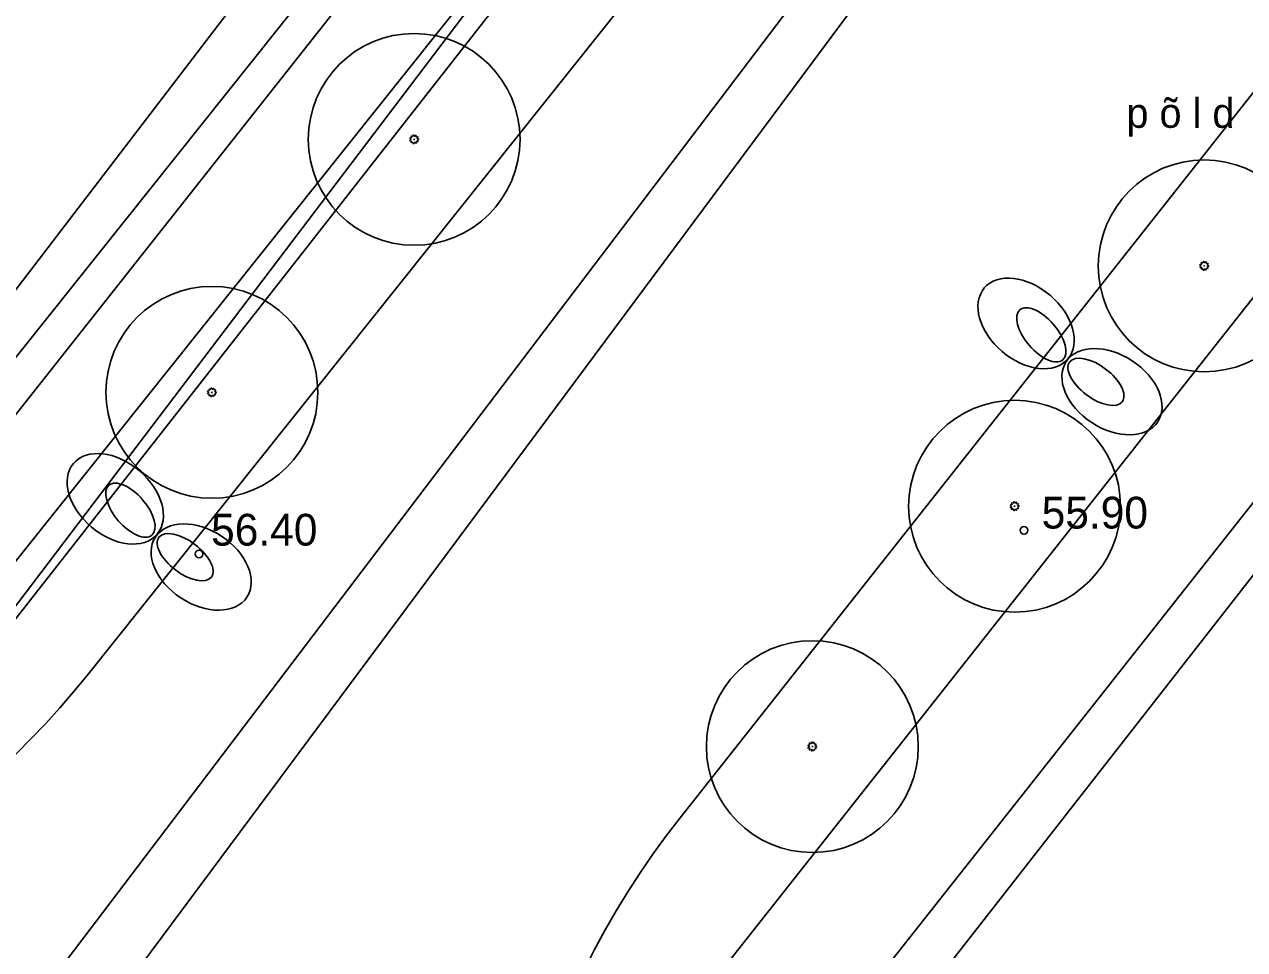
# Model space of a CAD drawing. Extents: x 9156 to 9809, y 2728 to 4000.
# Drawn here: x 9440.27 to 9469.07, y 3522.78 to 3544.62 of the extents above; entities that cross this region are included whole.
import ezdxf

# ---------------------------------------------------------------- set-up
doc = ezdxf.new("R2010")
doc.units = 0
for name, color, linetype in [('Level 12', 7, 'Continuous'), ('Level 14', 7, 'Continuous'), ('Level 15', 7, 'Continuous'), ('Level 16', 7, 'Continuous'), ('Level 17', 7, 'Continuous'), ('Level 18', 7, 'Continuous'), ('Level 54', 7, 'Continuous'), ('Level 56', 7, 'Continuous'), ('Level 7', 7, 'Continuous'), ('Level 8', 7, 'Continuous'), ('Level 9', 7, 'Continuous')]:
    doc.layers.add(name, color=color, linetype=linetype)

msp = doc.modelspace()

# ---------------------------------------------------------------- linework, layer by layer
at = {"layer": 'Level 12'}
msp.add_line((9472.329, 3573.455), (9435.481, 3524.854), dxfattribs=at)
at = {"layer": 'Level 14'}
msp.add_line((9427.489, 3501.526), (9484.383, 3578.032), dxfattribs=at)
at = {"layer": 'Level 15'}
msp.add_line((9435.211, 3524.4), (9458.77, 3554.464), dxfattribs=at)
at = {"layer": 'Level 16'}
msp.add_line((9432.07, 3510.41), (9469.372, 3559.57), dxfattribs=at)
at = {"layer": 'Level 17'}
for p, q in [((9504.212, 3582.406), (9456.099, 3521.498)), ((9506.566, 3580.546), (9458.461, 3519.649)), ((9427.374, 3519.354), (9458.182, 3558.332)), ((9428.56, 3522.344), (9455.51, 3556.115)), ((9432.973, 3523.064), (9457.855, 3554.244))]:
    msp.add_line(p, q, dxfattribs=at)
at = {"layer": 'Level 18'}
for p, q in [((9501.857, 3584.265), (9455.749, 3525.895)), ((9441.751, 3529.254), (9460.2, 3552.373))]:
    msp.add_line(p, q, dxfattribs=at)
for centre, start, end in [((9426.118, 3541.729), 233.8069, 321.4101), ((9471.443, 3513.498), 141.6938, 238.8019)]:
    msp.add_arc(centre, 20, start, end, dxfattribs=at)
at = {"layer": 'Level 54'}
for centre in [(9463.865, 3532.678), (9444.395, 3532.122)]:
    msp.add_circle(centre, 0.0909, dxfattribs=at)
at = {"layer": 'Level 56'}
for p, q in [((9501.857, 3584.265), (9455.749, 3525.895)), ((9504.212, 3582.406), (9456.099, 3521.498)), ((9506.566, 3580.546), (9458.461, 3519.649)), ((9428.56, 3522.344), (9455.51, 3556.115)), ((9432.973, 3523.064), (9457.855, 3554.244)), ((9441.751, 3529.254), (9460.2, 3552.373))]:
    msp.add_line(p, q, dxfattribs=at)
for centre, start, end in [((9426.118, 3541.729), 233.8069, 321.4101), ((9471.443, 3513.498), 141.6938, 238.8019)]:
    msp.add_arc(centre, 20, start, end, dxfattribs=at)
at = {"layer": 'Level 7'}
for p, q in [((9508.911, 3582.331), (9456.401, 3515.151)), ((9428.759, 3523.586), (9464.86, 3570.761))]:
    msp.add_line(p, q, dxfattribs=at)
at = {"layer": 'Level 8'}
for centre, major_axis, ratio in [((9463.915, 3537.563), (0.986, -0.837), 0.674652), ((9463.915, 3537.563), (0.986, -0.837), 0.674652), ((9463.915, 3537.563), (0.986, -0.837), 0.674652), ((9463.915, 3537.563), (0.986, -0.837), 0.674652), ((9464.274, 3537.294), (0.507, -0.589), 0.486914), ((9464.274, 3537.294), (0.507, -0.589), 0.486914), ((9464.274, 3537.294), (0.507, -0.589), 0.486914), ((9464.274, 3537.294), (0.507, -0.589), 0.486914), ((9465.942, 3535.952), (-1.081, 0.71), 0.674652), ((9465.942, 3535.952), (-1.081, 0.71), 0.674652), ((9465.942, 3535.952), (-1.081, 0.71), 0.674652), ((9465.942, 3535.952), (-1.081, 0.71), 0.674652), ((9465.564, 3536.185), (-0.62, 0.47), 0.486914), ((9465.564, 3536.185), (-0.62, 0.47), 0.486914), ((9465.564, 3536.185), (-0.62, 0.47), 0.486914), ((9465.564, 3536.185), (-0.62, 0.47), 0.486914), ((9442.418, 3533.423), (0.986, -0.837), 0.674652), ((9442.418, 3533.423), (0.986, -0.837), 0.674652), ((9442.418, 3533.423), (0.986, -0.837), 0.674652), ((9442.418, 3533.423), (0.986, -0.837), 0.674652), ((9442.776, 3533.154), (0.507, -0.589), 0.486914), ((9442.776, 3533.154), (0.507, -0.589), 0.486914), ((9442.776, 3533.154), (0.507, -0.589), 0.486914), ((9442.776, 3533.154), (0.507, -0.589), 0.486914), ((9444.445, 3531.812), (-1.081, 0.71), 0.674652), ((9444.445, 3531.812), (-1.081, 0.71), 0.674652), ((9444.445, 3531.812), (-1.081, 0.71), 0.674652), ((9444.445, 3531.812), (-1.081, 0.71), 0.674652), ((9444.067, 3532.045), (-0.62, 0.47), 0.486914), ((9444.067, 3532.045), (-0.62, 0.47), 0.486914), ((9444.067, 3532.045), (-0.62, 0.47), 0.486914), ((9444.067, 3532.045), (-0.62, 0.47), 0.486914)]:
    msp.add_ellipse(centre, major_axis=major_axis, ratio=ratio, dxfattribs=at)
at = {"layer": 'Level 9'}
for p, q in [((9449.394, 3541.92), (9449.372, 3541.923)), ((9449.372, 3541.894), (9449.393, 3541.898)), ((9449.38, 3541.95), (9449.4, 3541.942)), ((9449.4, 3541.876), (9449.38, 3541.866)), ((9449.395, 3541.843), (9449.412, 3541.857)), ((9449.412, 3541.96), (9449.396, 3541.974)), ((9449.417, 3541.993), (9449.429, 3541.974)), ((9449.429, 3541.842), (9449.417, 3541.824)), ((9449.45, 3541.984), (9449.443, 3542.005)), ((9449.443, 3541.812), (9449.449, 3541.833)), ((9449.482, 3541.907), (9449.461, 3541.907)), ((9449.472, 3541.829), (9449.471, 3541.808)), ((9449.472, 3542.009), (9449.472, 3541.987)), ((9449.472, 3541.897), (9449.472, 3541.918)), ((9449.493, 3541.984), (9449.499, 3542.005)), ((9449.499, 3541.811), (9449.494, 3541.833)), ((9449.514, 3541.841), (9449.526, 3541.823)), ((9449.525, 3541.993), (9449.515, 3541.974)), ((9449.531, 3541.96), (9449.548, 3541.974)), ((9449.548, 3541.843), (9449.532, 3541.858)), ((9449.563, 3541.95), (9449.544, 3541.94)), ((9449.544, 3541.876), (9449.564, 3541.867)), ((9449.55, 3541.919), (9449.571, 3541.923)), ((9449.571, 3541.895), (9449.55, 3541.898)), ((9468.041, 3538.934), (9468.019, 3538.937)), ((9468.019, 3538.908), (9468.04, 3538.912)), ((9468.027, 3538.964), (9468.047, 3538.956)), ((9468.047, 3538.89), (9468.027, 3538.88)), ((9468.042, 3538.857), (9468.059, 3538.871)), ((9468.059, 3538.974), (9468.043, 3538.988)), ((9468.064, 3539.007), (9468.075, 3538.988)), ((9468.076, 3538.856), (9468.064, 3538.838)), ((9468.097, 3538.998), (9468.09, 3539.019)), ((9468.129, 3538.921), (9468.108, 3538.921)), ((9468.118, 3539.023), (9468.118, 3539.001)), ((9468.119, 3538.911), (9468.119, 3538.932)), ((9468.14, 3538.998), (9468.146, 3539.019)), ((9468.161, 3538.856), (9468.173, 3538.838)), ((9468.172, 3539.007), (9468.162, 3538.988)), ((9468.178, 3538.974), (9468.194, 3538.988)), ((9468.195, 3538.857), (9468.179, 3538.872)), ((9468.21, 3538.964), (9468.191, 3538.954)), ((9468.191, 3538.89), (9468.21, 3538.882)), ((9468.197, 3538.933), (9468.218, 3538.937)), ((9468.218, 3538.909), (9468.197, 3538.912)), ((9468.09, 3538.826), (9468.096, 3538.847)), ((9468.118, 3538.844), (9468.118, 3538.822)), ((9468.146, 3538.826), (9468.141, 3538.847)), ((9444.607, 3535.979), (9444.627, 3535.97)), ((9444.639, 3535.989), (9444.622, 3536.003)), ((9444.643, 3536.021), (9444.655, 3536.003)), ((9444.676, 3536.012), (9444.67, 3536.033)), ((9444.698, 3536.037), (9444.698, 3536.015)), ((9444.719, 3536.012), (9444.725, 3536.033)), ((9444.752, 3536.022), (9444.741, 3536.003)), ((9444.757, 3535.989), (9444.774, 3536.003)), ((9444.789, 3535.978), (9444.77, 3535.969)), ((9444.62, 3535.948), (9444.598, 3535.951)), ((9444.598, 3535.923), (9444.62, 3535.926)), ((9444.626, 3535.904), (9444.607, 3535.894)), ((9444.622, 3535.871), (9444.638, 3535.885)), ((9444.656, 3535.87), (9444.643, 3535.852)), ((9444.669, 3535.84), (9444.675, 3535.861)), ((9444.709, 3535.936), (9444.688, 3535.936)), ((9444.698, 3535.858), (9444.697, 3535.836)), ((9444.698, 3535.925), (9444.698, 3535.946)), ((9444.726, 3535.84), (9444.72, 3535.861)), ((9444.74, 3535.87), (9444.752, 3535.852)), ((9444.775, 3535.872), (9444.758, 3535.886)), ((9444.77, 3535.905), (9444.79, 3535.896)), ((9444.776, 3535.948), (9444.797, 3535.952)), ((9444.798, 3535.923), (9444.776, 3535.927)), ((9463.565, 3533.261), (9463.544, 3533.264)), ((9463.544, 3533.235), (9463.565, 3533.239)), ((9463.552, 3533.291), (9463.572, 3533.283)), ((9463.571, 3533.217), (9463.552, 3533.207)), ((9463.584, 3533.301), (9463.567, 3533.315)), ((9463.567, 3533.184), (9463.583, 3533.198)), ((9463.589, 3533.334), (9463.6, 3533.315)), ((9463.601, 3533.183), (9463.589, 3533.165)), ((9463.614, 3533.153), (9463.62, 3533.174)), ((9463.622, 3533.325), (9463.615, 3533.346)), ((9463.654, 3533.248), (9463.633, 3533.248)), ((9463.643, 3533.171), (9463.642, 3533.149)), ((9463.643, 3533.35), (9463.643, 3533.328)), ((9463.643, 3533.238), (9463.643, 3533.259)), ((9463.665, 3533.325), (9463.671, 3533.346)), ((9463.671, 3533.153), (9463.665, 3533.174)), ((9463.685, 3533.183), (9463.697, 3533.165)), ((9463.697, 3533.334), (9463.686, 3533.315)), ((9463.703, 3533.301), (9463.719, 3533.315)), ((9463.72, 3533.184), (9463.704, 3533.199)), ((9463.735, 3533.291), (9463.715, 3533.281)), ((9463.715, 3533.217), (9463.735, 3533.209)), ((9463.721, 3533.26), (9463.743, 3533.264)), ((9463.743, 3533.236), (9463.721, 3533.239)), ((9458.81, 3527.628), (9458.794, 3527.642)), ((9458.815, 3527.661), (9458.827, 3527.642)), ((9458.848, 3527.652), (9458.841, 3527.673)), ((9458.87, 3527.677), (9458.87, 3527.655)), ((9458.891, 3527.652), (9458.897, 3527.673)), ((9458.923, 3527.661), (9458.913, 3527.642)), ((9458.929, 3527.628), (9458.946, 3527.642)), ((9458.792, 3527.588), (9458.77, 3527.591)), ((9458.77, 3527.562), (9458.791, 3527.566)), ((9458.778, 3527.618), (9458.798, 3527.61)), ((9458.798, 3527.544), (9458.778, 3527.534)), ((9458.793, 3527.511), (9458.81, 3527.525)), ((9458.827, 3527.51), (9458.815, 3527.492)), ((9458.841, 3527.48), (9458.847, 3527.501)), ((9458.88, 3527.575), (9458.859, 3527.575)), ((9458.87, 3527.498), (9458.869, 3527.476)), ((9458.87, 3527.565), (9458.87, 3527.586)), ((9458.897, 3527.48), (9458.892, 3527.501)), ((9458.912, 3527.51), (9458.924, 3527.492)), ((9458.946, 3527.511), (9458.93, 3527.526)), ((9458.961, 3527.618), (9458.942, 3527.608)), ((9458.942, 3527.544), (9458.962, 3527.536)), ((9458.948, 3527.587), (9458.969, 3527.591)), ((9458.969, 3527.563), (9458.948, 3527.566))]:
    msp.add_line(p, q, dxfattribs=at)
for centre in [(9449.472, 3541.907), (9468.119, 3538.921), (9444.698, 3535.936), (9463.643, 3533.248), (9458.87, 3527.575)]:
    msp.add_circle(centre, 2.5, dxfattribs=at)
for centre, radius, start, end in [((9449.472, 3541.908), 0.101, 155.3123, 171.7042), ((9449.472, 3541.908), 0.101, 187.9671, 204.8625), ((9449.472, 3541.908), 0.0788, 171.5431, 187.6203), ((9449.472, 3541.908), 0.101, 220.7122, 237.1166), ((9449.472, 3541.908), 0.101, 122.8434, 139.0222), ((9449.472, 3541.908), 0.0788, 138.6432, 154.5795), ((9449.472, 3541.908), 0.0788, 204.4529, 220.4774), ((9449.472, 3541.908), 0.0788, 105.9559, 123.0564), ((9449.472, 3541.908), 0.0788, 237.451, 253.0843), ((9449.472, 3541.908), 0.101, 90.0356, 106.342), ((9449.472, 3541.908), 0.101, 253.2952, 269.5718), ((9449.472, 3541.908), 0.0788, 74.31, 90.043), ((9449.472, 3541.908), 0.0788, 269.9461, 286.3473), ((9449.472, 3541.908), 0.101, 57.6108, 74.1981), ((9449.472, 3541.908), 0.101, 285.972, 302.5562), ((9449.472, 3541.908), 0.0788, 302.254, 320.086), ((9449.472, 3541.908), 0.0788, 41.2062, 56.7795), ((9449.472, 3541.908), 0.0788, 8.0619, 24.0332), ((9449.472, 3541.908), 0.0788, 336.0557, 352.7558), ((9449.472, 3541.908), 0.101, 24.5394, 40.9852), ((9449.472, 3541.908), 0.101, 319.7777, 336.0738), ((9449.472, 3541.908), 0.101, 352.27, 8.583), ((9468.119, 3538.922), 0.101, 155.3123, 171.7042), ((9468.119, 3538.922), 0.101, 187.9671, 204.8625), ((9468.119, 3538.922), 0.0788, 171.5431, 187.6203), ((9468.119, 3538.922), 0.101, 220.7122, 237.1166), ((9468.119, 3538.922), 0.101, 122.8434, 139.0222), ((9468.119, 3538.922), 0.0788, 138.6432, 154.5795), ((9468.119, 3538.922), 0.0788, 204.4529, 220.4774), ((9468.119, 3538.922), 0.0788, 105.9559, 123.0564), ((9468.119, 3538.922), 0.0788, 237.451, 253.0843), ((9468.119, 3538.922), 0.101, 90.0356, 106.342), ((9468.119, 3538.922), 0.0788, 74.31, 90.043), ((9468.119, 3538.922), 0.101, 57.6108, 74.1981), ((9468.119, 3538.922), 0.0788, 302.254, 320.086), ((9468.119, 3538.922), 0.0788, 41.2062, 56.7795), ((9468.119, 3538.922), 0.0788, 8.0619, 24.0332), ((9468.119, 3538.922), 0.0788, 336.0557, 352.7558), ((9468.119, 3538.922), 0.101, 24.5394, 40.9852), ((9468.119, 3538.922), 0.101, 319.7777, 336.0738), ((9468.119, 3538.922), 0.101, 352.27, 8.583), ((9468.119, 3538.922), 0.101, 253.2952, 269.5718), ((9468.119, 3538.922), 0.0788, 269.9461, 286.3473), ((9468.119, 3538.922), 0.101, 285.972, 302.5562), ((9444.698, 3535.937), 0.101, 155.3123, 171.7042), ((9444.698, 3535.937), 0.101, 122.8434, 139.0222), ((9444.698, 3535.937), 0.0788, 138.6432, 154.5795), ((9444.698, 3535.937), 0.0788, 105.9559, 123.0564), ((9444.698, 3535.937), 0.101, 90.0356, 106.342), ((9444.698, 3535.937), 0.0788, 74.31, 90.043), ((9444.698, 3535.937), 0.101, 57.6108, 74.1981), ((9444.698, 3535.937), 0.0788, 41.2062, 56.7795), ((9444.698, 3535.937), 0.101, 24.5394, 40.9852), ((9444.698, 3535.937), 0.101, 187.9671, 204.8625), ((9444.698, 3535.937), 0.0788, 171.5431, 187.6203), ((9444.698, 3535.937), 0.101, 220.7122, 237.1166), ((9444.698, 3535.937), 0.0788, 204.4529, 220.4774), ((9444.698, 3535.937), 0.0788, 237.451, 253.0843), ((9444.698, 3535.937), 0.101, 253.2952, 269.5718), ((9444.698, 3535.937), 0.0788, 269.9461, 286.3473), ((9444.698, 3535.937), 0.101, 285.972, 302.5562), ((9444.698, 3535.937), 0.0788, 302.254, 320.086), ((9444.698, 3535.937), 0.0788, 8.0619, 24.0332), ((9444.698, 3535.937), 0.0788, 336.0557, 352.7558), ((9444.698, 3535.937), 0.101, 319.7777, 336.0738), ((9444.698, 3535.937), 0.101, 352.27, 8.583), ((9463.643, 3533.249), 0.101, 155.3123, 171.7042), ((9463.643, 3533.249), 0.101, 187.9671, 204.8625), ((9463.643, 3533.249), 0.0788, 171.5431, 187.6203), ((9463.643, 3533.249), 0.101, 122.8434, 139.0222), ((9463.643, 3533.249), 0.101, 220.7122, 237.1166), ((9463.643, 3533.249), 0.0788, 204.4529, 220.4774), ((9463.643, 3533.249), 0.0788, 138.6432, 154.5795), ((9463.643, 3533.249), 0.0788, 105.9559, 123.0564), ((9463.643, 3533.249), 0.0788, 237.451, 253.0843), ((9463.643, 3533.249), 0.101, 253.2952, 269.5718), ((9463.643, 3533.249), 0.101, 90.0356, 106.342), ((9463.643, 3533.249), 0.0788, 74.31, 90.043), ((9463.643, 3533.249), 0.0788, 269.9461, 286.3473), ((9463.643, 3533.249), 0.101, 57.6108, 74.1981), ((9463.643, 3533.249), 0.101, 285.972, 302.5562), ((9463.643, 3533.249), 0.0788, 302.254, 320.086), ((9463.643, 3533.249), 0.0788, 41.2062, 56.7795), ((9463.643, 3533.249), 0.0788, 8.0619, 24.0332), ((9463.643, 3533.249), 0.0788, 336.0557, 352.7558), ((9463.643, 3533.249), 0.101, 24.5394, 40.9852), ((9463.643, 3533.249), 0.101, 319.7777, 336.0738), ((9463.643, 3533.249), 0.101, 352.27, 8.583), ((9458.87, 3527.576), 0.101, 122.8434, 139.0222), ((9458.87, 3527.576), 0.0788, 138.6432, 154.5795), ((9458.87, 3527.576), 0.0788, 105.9559, 123.0564), ((9458.87, 3527.576), 0.101, 90.0356, 106.342), ((9458.87, 3527.576), 0.0788, 74.31, 90.043), ((9458.87, 3527.576), 0.101, 57.6108, 74.1981), ((9458.87, 3527.576), 0.0788, 41.2062, 56.7795), ((9458.87, 3527.576), 0.101, 24.5394, 40.9852), ((9458.87, 3527.576), 0.101, 155.3123, 171.7042), ((9458.87, 3527.576), 0.101, 187.9671, 204.8625), ((9458.87, 3527.576), 0.0788, 171.5431, 187.6203), ((9458.87, 3527.576), 0.101, 220.7122, 237.1166), ((9458.87, 3527.576), 0.0788, 204.4529, 220.4774), ((9458.87, 3527.576), 0.0788, 237.451, 253.0843), ((9458.87, 3527.576), 0.101, 253.2952, 269.5718), ((9458.87, 3527.576), 0.0788, 269.9461, 286.3473), ((9458.87, 3527.576), 0.101, 285.972, 302.5562), ((9458.87, 3527.576), 0.0788, 302.254, 320.086), ((9458.87, 3527.576), 0.0788, 8.0619, 24.0332), ((9458.87, 3527.576), 0.0788, 336.0557, 352.7558), ((9458.87, 3527.576), 0.101, 319.7777, 336.0738), ((9458.87, 3527.576), 0.101, 352.27, 8.583)]:
    msp.add_arc(centre, radius, start, end, dxfattribs=at)

# ---------------------------------------------------------------- texts
at = {"layer": 'Level 54'}
for s, height, p in [('p õ l d', 0.7, (9466.283, 3542.18)), ('55.90', 0.75, (9464.282, 3532.722)), ('56.40', 0.75, (9444.679, 3532.319))]:
    msp.add_text(s, height=height, dxfattribs=at).set_placement(p)

doc.saveas('drawing.dxf')
